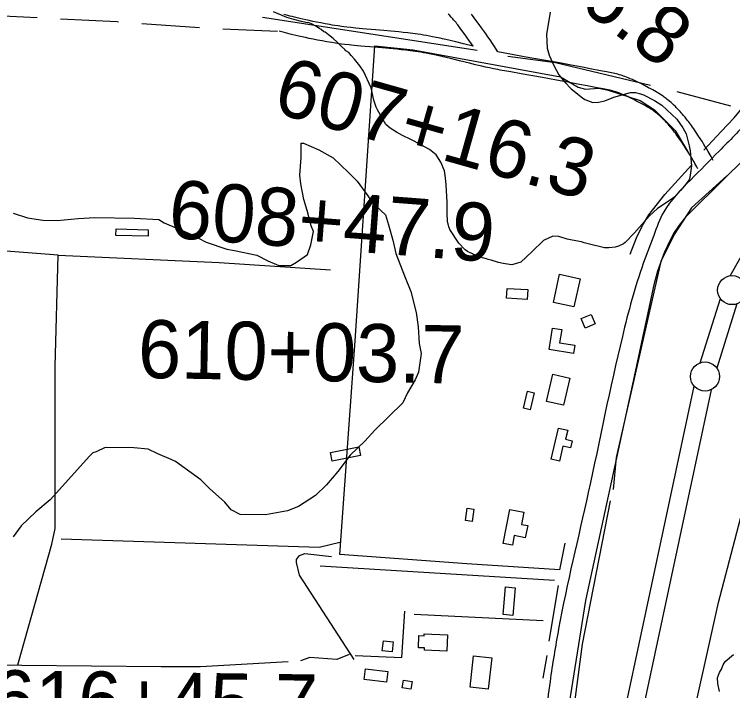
# Model space of a CAD drawing. Extents: x 3161564 to 3199464, y 849354 to 874788.
# Drawn here: x 3174366 to 3175603, y 868553 to 869718 of the extents above; entities that cross this region are included whole.
import ezdxf

# ---------------------------------------------------------------- set-up
doc = ezdxf.new("R2010")
doc.units = 0
for name, color, linetype in [('V-BLDG-OTLN', 7, 'Continuous'), ('V-LEVE-TOET', 7, 'Continuous'), ('V-ROAD-CNTR', 7, 'Continuous'), ('V-SITE-VEGE', 7, 'Continuous'), ('V-SURV-IDEN', 7, 'Continuous'), ('V-SURV-LINE', 7, 'Continuous'), ('V-TOPO-SHOR', 7, 'Continuous')]:
    doc.layers.add(name, color=color, linetype=linetype)

msp = doc.modelspace()

# ---------------------------------------------------------------- linework, layer by layer
at = {"layer": 'V-BLDG-OTLN'}
for points in [[(3174541, 869337.1), (3174541.2, 869348.3), (3174596.4, 869347), (3174596.1, 869335.8)], [(3175294, 869221.9), (3175304.7, 869270.4), (3175340, 869262.6), (3175329.3, 869214.1)], [(3175213.6, 869228.8), (3175214.5, 869245.8), (3175250, 869243.8), (3175249, 869226.9)], [(3175342, 869193.8), (3175359.1, 869201.1), (3175366.1, 869184.9), (3175349, 869177.5)], [(3175292.7, 869177.5), (3175308.4, 869174.9), (3175304.8, 869152.4), (3175331, 869148.1), (3175328.7, 869133.9), (3175286.7, 869140.7)], [(3175282.4, 869051.3), (3175293.1, 869098), (3175322.1, 869091.4), (3175311.5, 869044.6)], [(3175242.7, 869039.8), (3175249.6, 869068.9), (3175260.9, 869066.2), (3175254, 869037.1)], [(3175290, 868951.7), (3175302.7, 869005.5), (3175318.8, 869001.6), (3175315.1, 868986.1), (3175326.2, 868983.4), (3175323.3, 868971.2), (3175310.6, 868974.2), (3175304.4, 868948.3)], [(3174913.4, 868948.6), (3174910.4, 868963.4), (3174959.1, 868973.3), (3174962.1, 868958.4)], [(3175142.6, 868846), (3175145.4, 868867.3), (3175157, 868865.8), (3175154.1, 868844.4)], [(3175207.7, 868806.9), (3175219, 868865.2), (3175243.2, 868860.6), (3175239.2, 868839.6), (3175249.8, 868837.5), (3175245.7, 868816.5), (3175226.5, 868820.2), (3175223.4, 868803.9)], [(3175207.4, 868684.2), (3175211.6, 868731.9), (3175228.3, 868730.5), (3175224.1, 868682.7)], [(3175110.5, 868621.4), (3175071.9, 868623), (3175072.1, 868626.9), (3175061.6, 868627.3), (3175062.5, 868648.3), (3175071.6, 868647.9), (3175071.8, 868651.2), (3175111.7, 868649.5)], [(3174999.2, 868622), (3175001.3, 868639.2), (3175018.2, 868637.2), (3175016.2, 868620)], [(3175150.5, 868559.4), (3175156.8, 868613.3), (3175188.2, 868609.6), (3175181.9, 868555.7)], [(3174968.3, 868572.3), (3174970.5, 868590.7), (3175009, 868586.1), (3175006.8, 868567.8)], [(3175033.8, 868558.3), (3175035.8, 868571.3), (3175051, 868569), (3175048.9, 868556)]]:
    msp.add_lwpolyline(points, close=True, dxfattribs=at)
at = {"layer": 'V-LEVE-TOET'}
for points in [[(3175359.1, 867715.4), (3175439.3, 868019.7), (3175514.1, 868356.5), (3175516.8, 868380.6), (3175519.5, 868418.6), (3175524.1, 868459.8), (3175578.5, 868705.1), (3175676, 869077.7), (3175702.8, 869176.2), (3175720.7, 869235.1), (3175734.7, 869265.7), (3175754.2, 869289.7), (3175775.7, 869317.7), (3175798.6, 869353), (3175817.5, 869383.5), (3175913.2, 869512.3), (3175927.7, 869536.5), (3175937.5, 869556.5)], [(3175669.7, 869514.5), (3175591.5, 869437.7), (3175521.6, 869368.8), (3175510.5, 869354.9), (3175502, 869342.3), (3175494.3, 869327.9), (3175485, 869307.4), (3175473.6, 869275.8), (3175466.8, 869252.3), (3175430.4, 869081.2), (3175349.1, 868708.6), (3175302.9, 868416.3), (3175283.8, 868266.2), (3175274.1, 868237.4), (3175260.7, 868196.3), (3175244.6, 868149.5), (3175227.8, 868110.2), (3175154.6, 867830.1)]]:
    msp.add_lwpolyline(points, dxfattribs=at)
at = {"layer": 'V-ROAD-CNTR'}
for p, q in [((3174585.3, 869702.1), (3174685, 869694.9)), ((3174724.9, 869692.7), (3174819.3, 869689))]:
    msp.add_line(p, q, dxfattribs=at)
for points in [[(3174305.7, 869716.8), (3174358, 869714.5), (3174405.5, 869712.1)], [(3174445.5, 869710.1), (3174542.8, 869705.2), (3174545.4, 869705)], [(3175156.1, 869662.9), (3175139.4, 869667), (3175126.3, 869670.2), (3175116.3, 869672.6), (3175108.8, 869674.4), (3175103.2, 869675.7), (3175098.9, 869676.6), (3175092.5, 869678), (3175086.1, 869679.3), (3175080.7, 869680.3), (3175075.5, 869681.3), (3175070.5, 869682.1), (3175065.6, 869682.9), (3175060.9, 869683.6), (3175056.3, 869684.2), (3175051.9, 869684.8), (3175047.6, 869685.3), (3175043.4, 869685.8), (3175035.4, 869686.7), (3175027.9, 869687.5), (3175020.8, 869688.2), (3175014.2, 869688.8), (3175001.9, 869689.8), (3174980.5, 869691.6), (3174972.5, 869692.3), (3174965.6, 869692.9), (3174959.5, 869693.4), (3174954.2, 869694), (3174949.6, 869694.5), (3174945.5, 869694.9), (3174938.5, 869695.7), (3174933.2, 869696.4), (3174929.3, 869696.9), (3174923.4, 869697.8), (3174917.5, 869698.7), (3174913.2, 869699.4), (3174909.1, 869700.1), (3174901, 869701.5), (3174893.5, 869702.9), (3174886.4, 869704.2), (3174879.8, 869705.6), (3174873.7, 869706.9), (3174867.9, 869708.2), (3174862.5, 869709.4), (3174857.4, 869710.6), (3174852.7, 869711.7), (3174848.3, 869712.8), (3174844.1, 869713.9), (3174840.3, 869714.9), (3174836.7, 869715.9), (3174829.8, 869717.7)], [(3175156.1, 869662.9), (3175145.8, 869677.4), (3175142.1, 869682.5), (3175136.5, 869690.2), (3175130.9, 869697.9), (3175129.4, 869699.8), (3175128, 869701.7), (3175126.6, 869703.5), (3175125.1, 869705.2), (3175123.7, 869706.8), (3175122.3, 869708.4), (3175121, 869709.9), (3175118.2, 869712.9), (3175115.6, 869715.7), (3175113, 869718.3)], [(3175198.4, 869653.1), (3175191.3, 869664.2), (3175189.1, 869667.5), (3175185, 869673.7), (3175181.3, 869679.1), (3175178.1, 869683.7), (3175175.2, 869687.8), (3175170.2, 869694.8), (3175166.4, 869700.1), (3175160.7, 869707.9), (3175155, 869715.8), (3175153.2, 869718.1)], [(3175159.8, 869631.1), (3175149.8, 869633.5), (3175132.2, 869637.9), (3175119.2, 869641.1), (3175109.4, 869643.4), (3175102.1, 869645.2), (3175096.6, 869646.4), (3175092.5, 869647.3), (3175086.4, 869648.6), (3175080.2, 869649.9), (3175075.2, 869650.8), (3175070.4, 869651.7), (3175065.6, 869652.5), (3175061.1, 869653.2), (3175056.6, 869653.9), (3175052.2, 869654.5), (3175048, 869655), (3175043.9, 869655.6), (3175040, 869656), (3175032.2, 869656.9), (3175024.9, 869657.6), (3175018.1, 869658.3), (3175011.6, 869658.9), (3174999.4, 869659.9), (3174978, 869661.7), (3174969.9, 869662.4), (3174962.8, 869663), (3174956.6, 869663.6), (3174951.1, 869664.1), (3174946.4, 869664.6), (3174942.2, 869665.1), (3174934.8, 869665.9), (3174929.3, 869666.6), (3174925.2, 869667.2), (3174919, 869668.1), (3174912.8, 869669), (3174908.3, 869669.8), (3174904, 869670.5), (3174895.7, 869672), (3174887.9, 869673.4), (3174880.6, 869674.8), (3174873.7, 869676.2), (3174867.3, 869677.6), (3174861.3, 869678.9), (3174855.7, 869680.2), (3174850.5, 869681.4), (3174845.6, 869682.6), (3174841, 869683.7), (3174836.6, 869684.8), (3174832.6, 869685.9), (3174828.8, 869686.9), (3174821.8, 869688.8)], [(3175569.4, 869465.9), (3175567.5, 869469.4), (3175565.6, 869472.8), (3175563.9, 869475.9), (3175562.2, 869478.8), (3175560.6, 869481.5), (3175557.7, 869486.5), (3175555, 869490.9), (3175552.7, 869494.7), (3175550.6, 869498), (3175546.9, 869503.7), (3175544.1, 869507.9), (3175539.9, 869514.3), (3175535.6, 869520.6), (3175533.6, 869523.5), (3175531.7, 869526.2), (3175529.9, 869528.7), (3175528.2, 869531), (3175526.6, 869533.2), (3175525, 869535.2), (3175523.5, 869537.1), (3175520.7, 869540.6), (3175518.2, 869543.6), (3175516, 869546.2), (3175514, 869548.4), (3175512.2, 869550.4), (3175510.6, 869552.1), (3175507.8, 869555), (3175505.7, 869557.2), (3175504.1, 869558.9), (3175501.6, 869561.3), (3175499, 869563.7), (3175496.7, 869565.8), (3175494.4, 869567.8), (3175492.2, 869569.6), (3175490.2, 869571.3), (3175488.3, 869572.8), (3175486.5, 869574.1), (3175484.8, 869575.4), (3175483.1, 869576.6), (3175480.1, 869578.6), (3175477.4, 869580.4), (3175475, 869581.9), (3175472.9, 869583.2), (3175471.1, 869584.3), (3175467.9, 869586.2), (3175465.4, 869587.6), (3175461.8, 869589.6), (3175458.1, 869591.5), (3175451.1, 869595.2), (3175444.9, 869598.4), (3175442.1, 869599.7), (3175439.5, 869601), (3175437, 869602.2), (3175434.7, 869603.3), (3175432.5, 869604.3), (3175430.4, 869605.3), (3175426.5, 869607), (3175423, 869608.4), (3175419.9, 869609.6), (3175417.1, 869610.7), (3175414.7, 869611.5), (3175412.6, 869612.2), (3175410.6, 869612.9), (3175407.3, 869613.8), (3175404.8, 869614.6), (3175402.8, 869615.1), (3175399.9, 869615.8), (3175397, 869616.4), (3175385.4, 869618.7), (3175375.3, 869620.7), (3175357.6, 869624.1), (3175344.4, 869626.6), (3175324.5, 869630.4), (3175304.6, 869634), (3175280.3, 869638.4), (3175244, 869644.8), (3175225.9, 869648.1), (3175198.4, 869653.1)], [(3175542.9, 869451.7), (3175541.1, 869455.1), (3175539.4, 869458.2), (3175537.8, 869461.1), (3175536.2, 869463.8), (3175534.8, 869466.3), (3175532, 869471), (3175529.5, 869475.2), (3175527.2, 869478.7), (3175525.3, 869481.8), (3175521.7, 869487.3), (3175519.1, 869491.4), (3175515, 869497.6), (3175510.8, 869503.7), (3175509, 869506.4), (3175507.3, 869508.8), (3175505.7, 869511), (3175504.2, 869513.1), (3175502.7, 869515), (3175501.3, 869516.8), (3175500.1, 869518.4), (3175497.6, 869521.5), (3175495.4, 869524.1), (3175493.4, 869526.4), (3175491.6, 869528.4), (3175490.1, 869530.1), (3175488.7, 869531.6), (3175486.3, 869534.2), (3175484.4, 869536.1), (3175483, 869537.5), (3175480.8, 869539.6), (3175478.6, 869541.7), (3175476.7, 869543.4), (3175474.9, 869545), (3175473.2, 869546.4), (3175471.6, 869547.8), (3175470, 869549), (3175468.5, 869550.1), (3175467.2, 869551.1), (3175465.9, 869552), (3175463.3, 869553.8), (3175461.1, 869555.3), (3175459.1, 869556.5), (3175457.3, 869557.6), (3175455.8, 869558.6), (3175452.9, 869560.2), (3175450.8, 869561.4), (3175447.6, 869563.2), (3175444.2, 869565), (3175437.3, 869568.5), (3175431.3, 869571.6), (3175428.8, 869572.9), (3175426.4, 869574), (3175424.1, 869575.1), (3175422, 869576.1), (3175420.1, 869577), (3175418.2, 869577.8), (3175414.8, 869579.4), (3175411.8, 869580.6), (3175409.2, 869581.6), (3175406.9, 869582.5), (3175404.9, 869583.2), (3175403.2, 869583.7), (3175401.7, 869584.2), (3175399, 869585), (3175397, 869585.6), (3175395.6, 869586), (3175393.3, 869586.5), (3175391, 869587), (3175379.6, 869589.3), (3175369.6, 869591.2), (3175352, 869594.7), (3175338.8, 869597.2), (3175319, 869600.9), (3175299.2, 869604.5), (3175275.1, 869608.8), (3175238.8, 869615.3), (3175220.6, 869618.6), (3175202.4, 869621.9), (3175198.5, 869622.6), (3175194.7, 869623.3), (3175191, 869624.1), (3175183.9, 869625.6), (3175177.2, 869627), (3175171.1, 869628.4), (3175165.3, 869629.8), (3175159.9, 869631.1)]]:
    msp.add_lwpolyline(points, dxfattribs=at)
msp.add_spline([(3176214.4, 872288), (3176116.8, 871676.9), (3176098.4, 871490.9), (3176090.7, 871415.9), (3176074.1, 871299.5), (3176058.2, 871187.5), (3176040.2, 871070.2), (3175999.5, 870899), (3175937.9, 870603.4), (3175884.9, 870365.8), (3175824.8, 870091.5), (3175790, 869942.8), (3175763.6, 869810), (3175731.1, 869705.4), (3175702.3, 869636.9), (3175675, 869598.5), (3175631, 869537.2), (3175579.4, 869482.4), (3175530.5, 869432.7), (3175484.1, 869377.7), (3175466.8, 869337.1), (3175448.9, 869288.9), (3175412.8, 869163.3), (3175354.2, 868894.7), (3175303.1, 868660), (3175288.3, 868569), (3175271.6, 868449), (3175249.1, 868331), (3175221.8, 868196), (3175175.8, 868026.9), (3175130.1, 867867), (3175087.9, 867676.4), (3175040.2, 867488.1), (3174985.4, 867232.3), (3174937.6, 866993.6), (3174859.7, 866658.8), (3174804.6, 866380.1), (3174764.5, 866230.5), (3174736.4, 866088.4)], degree=3, dxfattribs=at)
at = {"layer": 'V-SITE-VEGE'}
for points in [[(3175111.3, 869394.3), (3175109.7, 869424), (3175108.3, 869436.1), (3175106.5, 869448.2), (3175100.5, 869463.5), (3175092.5, 869476), (3175080.5, 869485.2), (3175053.1, 869499.9), (3175048.4, 869502.3), (3175034.5, 869509.2), (3175023.7, 869514.8), (3175013.2, 869521.5), (3175005.5, 869528.3), (3174991.5, 869553.4), (3174989.2, 869557.7), (3174984.7, 869570.2), (3174980.3, 869591.3), (3174967.4, 869620), (3174960.9, 869629), (3174951.7, 869640.4), (3174946, 869646.8), (3174941.7, 869651.9), (3174936.7, 869654.7), (3174935.2, 869657.4), (3174929.4, 869662.2), (3174921.7, 869670.1), (3174914.8, 869676.4), (3174907.1, 869682.7), (3174900.9, 869687.1), (3174898.6, 869687.9), (3174894.3, 869691.5), (3174892, 869692.7), (3174888.2, 869695.5), (3174880, 869700.3), (3174872.3, 869703.9), (3174870.3, 869703.1), (3174867.6, 869703.5), (3174860.2, 869705.2), (3174847, 869708.9), (3174835.4, 869712.6), (3174812.1, 869721.8)], [(3175288.7, 869721.6), (3175282, 869683.1), (3175283.2, 869659.7), (3175287, 869647.2), (3175294.9, 869629.9), (3175303.6, 869613.8), (3175313.6, 869600.8), (3175324.7, 869589.4), (3175344.4, 869573.9), (3175348.3, 869571.2), (3175361.8, 869565.9), (3175371.6, 869566.5), (3175382.5, 869569.1), (3175398.2, 869575.2), (3175426.8, 869583.3), (3175435.3, 869583.2), (3175444.3, 869581.1), (3175449.3, 869579.1), (3175468.3, 869569.5), (3175481, 869561.2), (3175506.4, 869537), (3175516.7, 869522.1), (3175522.4, 869511.9), (3175527.6, 869491.6), (3175529.5, 869483), (3175531.8, 869457.2), (3175528.8, 869437), (3175527.6, 869433.1), (3175519.7, 869422.7), (3175512.9, 869414.2), (3175503.4, 869403.8), (3175493.2, 869396.5), (3175473.5, 869383.2), (3175459.7, 869370.9), (3175433.6, 869341.6), (3175417.4, 869324.7), (3175414.7, 869322.8), (3175406.4, 869318.6), (3175400.5, 869316.7), (3175389.6, 869315.7), (3175381.8, 869315.8), (3175351.5, 869323.3), (3175346.9, 869324.5), (3175342.2, 869326.1), (3175326.3, 869329.1), (3175317.7, 869330.7), (3175303.4, 869335.2), (3175292.9, 869336.1), (3175277.2, 869328.2), (3175257, 869308.6), (3175238.1, 869291.3), (3175222.8, 869286.4), (3175218.5, 869287.3), (3175207.6, 869288.6), (3175199.5, 869290.6), (3175187.1, 869294.7), (3175181.6, 869295.9), (3175178.9, 869296.8), (3175176.6, 869297.2), (3175174.7, 869298), (3175171.9, 869298.4), (3175163.4, 869302), (3175156.8, 869304.1), (3175154.9, 869305.3), (3175148.7, 869308.1), (3175146, 869309.7), (3175142.1, 869312.5), (3175131.4, 869323.5), (3175115.7, 869347.1), (3175113.8, 869351.8), (3175112, 869361.6), (3175111, 869374.8), (3175111.3, 869394.3)], [(3174415.1, 869363.3), (3174439.8, 869363), (3174476, 869366.3), (3174504.5, 869367.8), (3174573, 869366.9), (3174614.8, 869364.5), (3174624.2, 869358.6), (3174669.6, 869339), (3174696.1, 869325.3), (3174732.1, 869313.5), (3174745.3, 869311.4), (3174783.3, 869303.3), (3174802.2, 869293.5), (3174821.1, 869285.6), (3174842, 869285.4), (3174851.6, 869290.9), (3174870.8, 869304), (3174876.7, 869321), (3174880.8, 869343.8), (3174877.1, 869353.4), (3174869.9, 869380.1), (3174864.4, 869399.2), (3174859.1, 869425.9), (3174857.4, 869441.1), (3174859.7, 869471.5), (3174860, 869496.2), (3174863.8, 869496.2), (3174890.3, 869484.4), (3174914.8, 869470.8), (3174941.1, 869445.7), (3174956.1, 869430.3), (3174974.8, 869405.3), (3174982.3, 869393.8), (3175004.8, 869372.6), (3175010.3, 869355.4), (3175017.6, 869328.7), (3175023, 869305.8), (3175037.7, 869267.5), (3175048.7, 869240.8), (3175057.7, 869204.5), (3175061.2, 869179.7), (3175062.7, 869151.2), (3175066.3, 869134), (3175062.1, 869101.7), (3175056.2, 869088.5), (3175042.6, 869065.9), (3175034.7, 869048.8), (3174986.6, 869001.9), (3174969.2, 868983.1), (3174944.1, 868958.8), (3174922.8, 868930.5), (3174903.5, 868907.9), (3174884.3, 868889.2), (3174855.5, 868870.6), (3174836.4, 868863.2), (3174798.2, 868856.1), (3174754.5, 868856.7), (3174739.4, 868864.5), (3174728.1, 868878), (3174701.8, 868901.1), (3174686.8, 868916.5), (3174643.5, 868947.6), (3174635.9, 868951.5), (3174613.2, 868961.3), (3174596.2, 868969.1), (3174571.5, 868971.3), (3174522.1, 868972), (3174506.8, 868964.6), (3174501, 868962.8), (3174495.3, 868957.1), (3174427.7, 868882), (3174402.7, 868861.4), (3174377.6, 868837), (3174364.1, 868818.2)], [(3174363.9, 869375.4), (3174388.5, 869367.5), (3174415.1, 869363.3)], [(3175579.9, 868551.8), (3175577.2, 868565.9), (3175576.8, 868575.5), (3175579.8, 868584.4), (3175583.4, 868590.2), (3175586.6, 868597.5), (3175589.9, 868603.6), (3175604.2, 868615.7)]]:
    msp.add_lwpolyline(points, dxfattribs=at)
at = {"layer": 'V-SURV-LINE'}
for points in [[(3175598.6, 869267.7), (3175643.7, 869347.4)], [(3175546.8, 869117.8), (3175581.5, 869228.3)], [(3175610.1, 869219.4), (3175575.4, 869108.8)], [(3175410.9, 868489), (3175536.3, 869077.8)], [(3175565.6, 869071.5), (3175440.3, 868482.7)]]:
    msp.add_lwpolyline(points, dxfattribs=at)
for centre in [(3175601.8, 869242.9), (3175555.1, 869094.2)]:
    msp.add_circle(centre, 25, dxfattribs=at)
at = {"layer": 'V-TOPO-SHOR'}
for p, q in [((3175162.6, 869655.6), (3174793.1, 869712.5)), ((3175599.6, 869559.7), (3175507.2, 869584.6)), ((3174441.4, 869303), (3174022.1, 869335)), ((3174892.6, 868768.3), (3175295.8, 868743.5)), ((3175286.9, 868638.7), (3175302.9, 868734.6)), ((3175054.2, 868684.8), (3175276.3, 868674.2)), ((3175276.3, 868574.7), (3175283.4, 868613.8))]:
    msp.add_line(p, q, dxfattribs=at)
for points in [[(3175553.1, 869483.9), (3175583, 869516.1), (3175605.3, 869539.8), (3175629.3, 869569.1), (3175644.2, 869588.9), (3175660.3, 869614.5), (3175677.1, 869643), (3175690.9, 869665.8), (3175702.7, 869689.2), (3175708.3, 869706.5)], [(3175313.6, 868807.4), (3175304.7, 868761.2), (3175144.8, 868771.9), (3174926.3, 868787.9), (3174953, 869155.6), (3174986.7, 869663.6), (3175052.4, 869656.5), (3175306.5, 869610.3), (3175336.7, 869592.6), (3175349.1, 869589), (3175372.2, 869590.8), (3175388.2, 869587.2), (3175443.2, 869569.5), (3175468.1, 869553.5), (3175503.6, 869518), (3175525, 869482.4)], [(3175461, 869595.2), (3175297.6, 869634.3), (3175215.9, 869645)], [(3175426.2, 869305), (3175437.4, 869332.7), (3175447.6, 869354.1), (3175458.2, 869372.3), (3175486.2, 869407.5), (3175531.7, 869458.1)], [(3175592.5, 869439.8), (3175532.1, 869384.7), (3175501.9, 869338.5), (3175478.8, 869292.4), (3175402.4, 868954.8), (3175397.1, 868899.8)], [(3174436, 869111.2), (3174441.4, 869303), (3174718.5, 869290.6), (3174910.3, 869278.1)], [(3174372.1, 868597.8), (3174430.7, 868805.6), (3174436, 868832.3), (3174436, 869111.2)], [(3175391.7, 868880.2), (3175343.8, 868633.3), (3175315.3, 868420.2), (3175315.3, 868402.4), (3175301.1, 868338.4)], [(3174446.7, 868814.5), (3174890.8, 868800.3), (3174926.3, 868809.2)], [(3174951.2, 868606.7), (3174857, 868752.3), (3174851.7, 868773.7), (3174851.7, 868779), (3174857, 868786.1), (3174865.9, 868789.6), (3174912.1, 868784.3)], [(3174953, 868613.8), (3175032.9, 868610.2), (3175038.2, 868690.2)], [(3174942.3, 868615.6), (3174921, 868606.7), (3174874.8, 868610.2), (3174858.8, 868604.9)], [(3174837.5, 868603.1), (3174686.5, 868594.2), (3174619, 868594.2), (3174258.4, 868597.8)]]:
    msp.add_lwpolyline(points, dxfattribs=at)

# ---------------------------------------------------------------- texts
at = {"layer": 'V-SURV-IDEN'}
for s, rotation, p in [('605+76.8', 323.2507, (3175033, 869957.3)), ('607+16.3', 344.2405, (3174807.8, 869550.3)), ('608+47.9', 355.6468, (3174629.3, 869333.6)), ('610+03.7', 358.9763, (3174578.2, 869091.9)), ('616+45.7', 359.2016, (3174326.4, 868488.9))]:
    msp.add_text(s, height=100, rotation=rotation, dxfattribs=at).set_placement(p)

doc.saveas('drawing.dxf')
